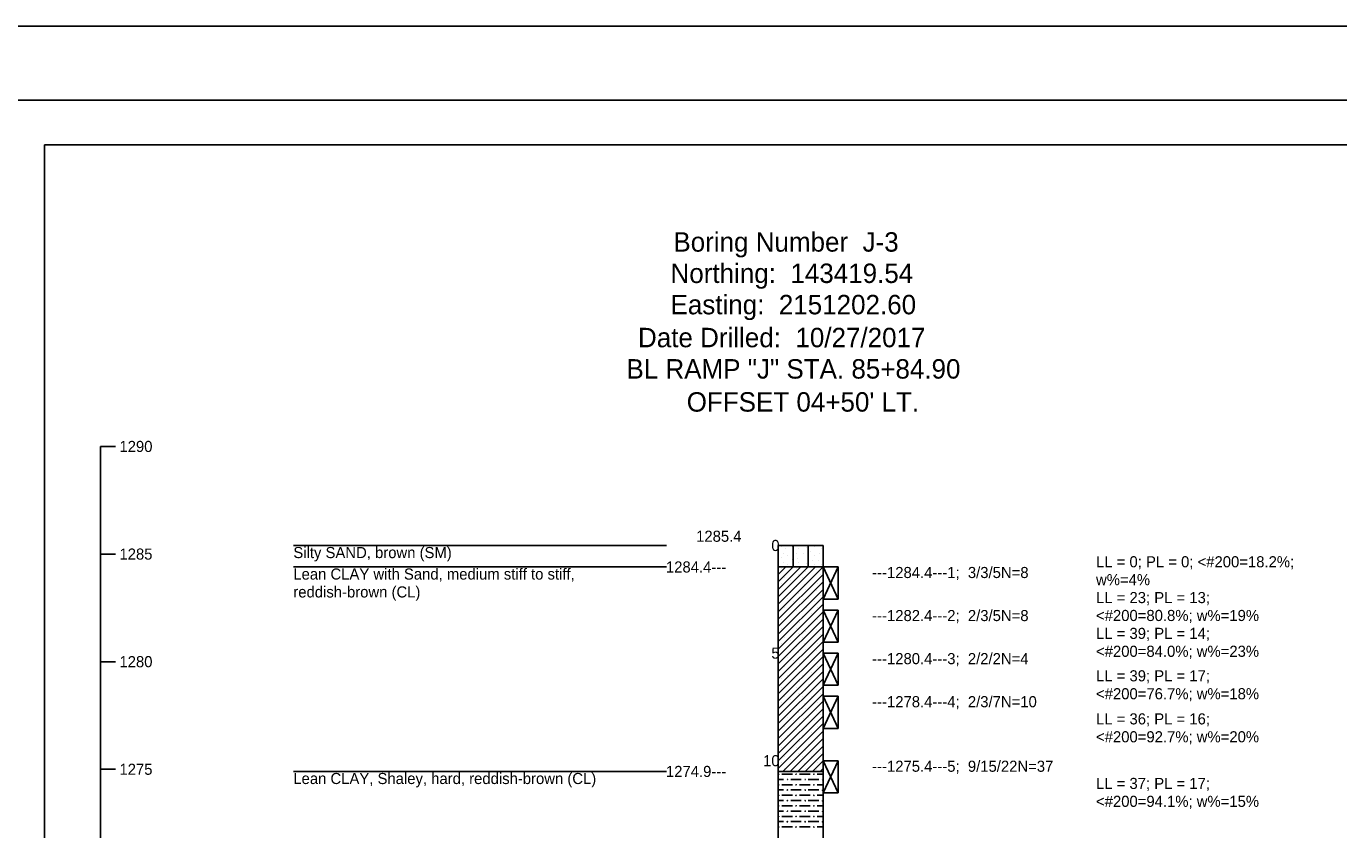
# Model space of a CAD drawing. Extents: x 2150148.6 to 2150220.1, y 143803.7 to 143875.1.
# Drawn here: x 2150167.96 to 2150182.61, y 143824.71 to 143833.69 of the extents above; entities that cross this region are included whole.
import ezdxf

# ---------------------------------------------------------------- set-up
doc = ezdxf.new("R2010")
doc.units = 0
for name, color, linetype in [('Default', 7, 'Continuous'), ('SHT_Plot_Shape_Full', 7, 'Continuous'), ('SHT_Plot_Shape_Half', 7, 'Continuous'), ('SHT_Sheet_Border', 7, 'Continuous')]:
    doc.layers.add(name, color=color, linetype=linetype)

# ---------------------------------------------------------------- blocks, each defined once
blk = doc.blocks.new('POINT_DISPLAY')
at = {"layer": 'Default'}
blk.add_line((0, 0), (0, 0), dxfattribs=at)

msp = doc.modelspace()

# ---------------------------------------------------------------- linework, layer by layer
at = {"layer": 'Default'}
msp.add_line((2150168.788, 143815.773), (2150168.788, 143828.994), dxfattribs=at)
for points in [[(2150168.788, 143828.994), (2150168.955, 143828.994)], [(2150170.94, 143827.888), (2150175.106, 143827.888)], [(2150176.356, 143827.888), (2150176.356, 143815.869)], [(2150176.356, 143827.888), (2150176.856, 143827.888)], [(2150176.523, 143827.648), (2150176.523, 143827.888)], [(2150176.69, 143827.648), (2150176.69, 143827.888)], [(2150176.856, 143827.888), (2150176.856, 143815.869)], [(2150168.788, 143827.792), (2150168.955, 143827.792)], [(2150170.94, 143827.648), (2150175.106, 143827.648)], [(2150176.356, 143827.648), (2150176.856, 143827.648)], [(2150176.356, 143827.564), (2150176.44, 143827.648)], [(2150176.356, 143827.481), (2150176.523, 143827.648)], [(2150176.356, 143827.398), (2150176.606, 143827.648)], [(2150176.356, 143827.314), (2150176.69, 143827.648)], [(2150176.356, 143827.231), (2150176.773, 143827.648)], [(2150176.356, 143827.148), (2150176.856, 143827.648)], [(2150176.356, 143827.064), (2150176.856, 143827.564)], [(2150176.856, 143827.648), (2150177.023, 143827.287)], [(2150176.856, 143827.287), (2150177.023, 143827.648)], [(2150176.856, 143827.648), (2150177.023, 143827.648)], [(2150177.023, 143827.287), (2150177.023, 143827.648)], [(2150176.356, 143826.981), (2150176.856, 143827.481)], [(2150176.356, 143826.898), (2150176.856, 143827.398)], [(2150176.356, 143826.814), (2150176.856, 143827.314)], [(2150176.356, 143826.731), (2150176.856, 143827.231)], [(2150176.856, 143827.287), (2150177.023, 143827.287)], [(2150176.356, 143826.648), (2150176.856, 143827.148)], [(2150176.856, 143827.167), (2150177.023, 143826.806)], [(2150176.856, 143826.806), (2150177.023, 143827.167)], [(2150176.856, 143827.167), (2150177.023, 143827.167)], [(2150177.023, 143826.806), (2150177.023, 143827.167)], [(2150176.356, 143826.564), (2150176.856, 143827.064)], [(2150176.356, 143826.481), (2150176.856, 143826.981)], [(2150176.356, 143826.398), (2150176.856, 143826.898)], [(2150176.356, 143826.314), (2150176.856, 143826.814)], [(2150176.856, 143826.806), (2150177.023, 143826.806)], [(2150176.356, 143826.231), (2150176.856, 143826.731)], [(2150176.356, 143826.148), (2150176.856, 143826.648)], [(2150176.856, 143826.686), (2150177.023, 143826.326)], [(2150176.856, 143826.326), (2150177.023, 143826.686)], [(2150176.856, 143826.686), (2150177.023, 143826.686)], [(2150177.023, 143826.326), (2150177.023, 143826.686)], [(2150168.788, 143826.59), (2150168.955, 143826.59)], [(2150176.356, 143826.064), (2150176.856, 143826.564)], [(2150176.356, 143825.981), (2150176.856, 143826.481)], [(2150176.356, 143825.898), (2150176.856, 143826.398)], [(2150176.356, 143825.814), (2150176.856, 143826.314)], [(2150176.356, 143825.731), (2150176.856, 143826.231)], [(2150176.856, 143826.326), (2150177.023, 143826.326)], [(2150176.856, 143826.205), (2150177.023, 143825.845)], [(2150176.856, 143825.845), (2150177.023, 143826.205)], [(2150176.856, 143826.205), (2150177.023, 143826.205)], [(2150177.023, 143825.845), (2150177.023, 143826.205)], [(2150176.356, 143825.648), (2150176.856, 143826.148)], [(2150176.356, 143825.564), (2150176.856, 143826.064)], [(2150176.356, 143825.481), (2150176.856, 143825.981)], [(2150176.356, 143825.398), (2150176.856, 143825.898)], [(2150176.406, 143825.364), (2150176.856, 143825.814)], [(2150176.856, 143825.845), (2150177.023, 143825.845)], [(2150176.489, 143825.364), (2150176.856, 143825.731)], [(2150176.573, 143825.364), (2150176.856, 143825.648)], [(2150176.656, 143825.364), (2150176.856, 143825.564)], [(2150176.739, 143825.364), (2150176.856, 143825.481)], [(2150176.856, 143825.484), (2150177.023, 143825.124)], [(2150176.856, 143825.124), (2150177.023, 143825.484)], [(2150176.856, 143825.484), (2150177.023, 143825.484)], [(2150177.023, 143825.124), (2150177.023, 143825.484)], [(2150168.788, 143825.388), (2150168.955, 143825.388)], [(2150170.94, 143825.364), (2150175.106, 143825.364)], [(2150176.356, 143825.364), (2150176.856, 143825.364)], [(2150176.356, 143825.335), (2150176.36, 143825.335), (2150176.36, 143825.331), (2150176.356, 143825.335)], [(2150176.396, 143825.335), (2150176.514, 143825.335)], [(2150176.553, 143825.335), (2150176.557, 143825.335), (2150176.553, 143825.331), (2150176.553, 143825.335)], [(2150176.593, 143825.335), (2150176.711, 143825.335)], [(2150176.75, 143825.335), (2150176.754, 143825.335), (2150176.754, 143825.331), (2150176.75, 143825.335)], [(2150176.789, 143825.335), (2150176.856, 143825.335)], [(2150176.823, 143825.364), (2150176.856, 143825.398)], [(2150176.356, 143825.275), (2150176.415, 143825.275)], [(2150176.356, 143825.216), (2150176.36, 143825.216), (2150176.36, 143825.212), (2150176.356, 143825.216)], [(2150176.396, 143825.216), (2150176.514, 143825.216)], [(2150176.455, 143825.275), (2150176.459, 143825.275), (2150176.455, 143825.272), (2150176.455, 143825.275)], [(2150176.494, 143825.275), (2150176.612, 143825.275)], [(2150176.553, 143825.216), (2150176.557, 143825.216), (2150176.553, 143825.212), (2150176.553, 143825.216)], [(2150176.593, 143825.216), (2150176.711, 143825.216)], [(2150176.652, 143825.275), (2150176.656, 143825.275), (2150176.656, 143825.272), (2150176.652, 143825.275)], [(2150176.691, 143825.275), (2150176.75, 143825.275)], [(2150176.75, 143825.275), (2150176.809, 143825.275)], [(2150176.75, 143825.216), (2150176.754, 143825.216), (2150176.754, 143825.212), (2150176.75, 143825.216)], [(2150176.789, 143825.216), (2150176.856, 143825.216)], [(2150176.848, 143825.275), (2150176.852, 143825.275), (2150176.848, 143825.272), (2150176.848, 143825.275)], [(2150176.356, 143825.157), (2150176.415, 143825.157)], [(2150176.356, 143825.098), (2150176.36, 143825.098), (2150176.36, 143825.094), (2150176.356, 143825.098)], [(2150176.356, 143825.039), (2150176.415, 143825.039)], [(2150176.396, 143825.098), (2150176.514, 143825.098)], [(2150176.455, 143825.157), (2150176.459, 143825.157), (2150176.455, 143825.153), (2150176.455, 143825.157)], [(2150176.455, 143825.039), (2150176.459, 143825.039), (2150176.455, 143825.035), (2150176.455, 143825.039)], [(2150176.494, 143825.157), (2150176.612, 143825.157)], [(2150176.494, 143825.039), (2150176.612, 143825.039)], [(2150176.553, 143825.098), (2150176.557, 143825.098), (2150176.553, 143825.094), (2150176.553, 143825.098)], [(2150176.593, 143825.098), (2150176.711, 143825.098)], [(2150176.652, 143825.157), (2150176.656, 143825.157), (2150176.656, 143825.153), (2150176.652, 143825.157)], [(2150176.652, 143825.039), (2150176.656, 143825.039), (2150176.656, 143825.035), (2150176.652, 143825.039)], [(2150176.691, 143825.157), (2150176.75, 143825.157)], [(2150176.691, 143825.039), (2150176.75, 143825.039)], [(2150176.75, 143825.157), (2150176.809, 143825.157)], [(2150176.75, 143825.098), (2150176.754, 143825.098), (2150176.754, 143825.094), (2150176.75, 143825.098)], [(2150176.75, 143825.039), (2150176.809, 143825.039)], [(2150176.789, 143825.098), (2150176.856, 143825.098)], [(2150176.848, 143825.157), (2150176.852, 143825.157), (2150176.848, 143825.153), (2150176.848, 143825.157)], [(2150176.848, 143825.039), (2150176.852, 143825.039), (2150176.848, 143825.035), (2150176.848, 143825.039)], [(2150176.856, 143825.124), (2150177.023, 143825.124)], [(2150176.356, 143824.98), (2150176.36, 143824.98), (2150176.36, 143824.976), (2150176.356, 143824.98)], [(2150176.356, 143824.921), (2150176.415, 143824.921)], [(2150176.396, 143824.98), (2150176.514, 143824.98)], [(2150176.455, 143824.921), (2150176.459, 143824.921), (2150176.455, 143824.917), (2150176.455, 143824.921)], [(2150176.494, 143824.921), (2150176.612, 143824.921)], [(2150176.553, 143824.98), (2150176.557, 143824.98), (2150176.553, 143824.976), (2150176.553, 143824.98)], [(2150176.593, 143824.98), (2150176.711, 143824.98)], [(2150176.652, 143824.921), (2150176.656, 143824.921), (2150176.656, 143824.917), (2150176.652, 143824.921)], [(2150176.691, 143824.921), (2150176.75, 143824.921)], [(2150176.75, 143824.98), (2150176.754, 143824.98), (2150176.754, 143824.976), (2150176.75, 143824.98)], [(2150176.75, 143824.921), (2150176.809, 143824.921)], [(2150176.789, 143824.98), (2150176.856, 143824.98)], [(2150176.848, 143824.921), (2150176.852, 143824.921), (2150176.848, 143824.917), (2150176.848, 143824.921)], [(2150176.356, 143824.862), (2150176.36, 143824.862), (2150176.36, 143824.858), (2150176.356, 143824.862)], [(2150176.356, 143824.803), (2150176.415, 143824.803)], [(2150176.356, 143824.744), (2150176.36, 143824.744), (2150176.36, 143824.74), (2150176.356, 143824.744)], [(2150176.396, 143824.862), (2150176.514, 143824.862)], [(2150176.396, 143824.744), (2150176.514, 143824.744)], [(2150176.455, 143824.803), (2150176.459, 143824.803), (2150176.455, 143824.799), (2150176.455, 143824.803)], [(2150176.494, 143824.803), (2150176.612, 143824.803)], [(2150176.553, 143824.862), (2150176.557, 143824.862), (2150176.553, 143824.858), (2150176.553, 143824.862)], [(2150176.553, 143824.744), (2150176.557, 143824.744), (2150176.553, 143824.74), (2150176.553, 143824.744)], [(2150176.593, 143824.862), (2150176.711, 143824.862)], [(2150176.593, 143824.744), (2150176.711, 143824.744)], [(2150176.652, 143824.803), (2150176.656, 143824.803), (2150176.656, 143824.799), (2150176.652, 143824.803)], [(2150176.691, 143824.803), (2150176.75, 143824.803)], [(2150176.75, 143824.862), (2150176.754, 143824.862), (2150176.754, 143824.858), (2150176.75, 143824.862)], [(2150176.75, 143824.803), (2150176.809, 143824.803)], [(2150176.75, 143824.744), (2150176.754, 143824.744), (2150176.754, 143824.74), (2150176.75, 143824.744)], [(2150176.789, 143824.862), (2150176.856, 143824.862)], [(2150176.789, 143824.744), (2150176.856, 143824.744)], [(2150176.848, 143824.803), (2150176.852, 143824.803), (2150176.848, 143824.799), (2150176.848, 143824.803)]]:
    msp.add_lwpolyline(points, dxfattribs=at)
at = {"layer": 'SHT_Plot_Shape_Full'}
msp.add_lwpolyline([(2150164.575, 143833.688), (2150200.575, 143833.688), (2150200.575, 143809.688), (2150164.575, 143809.688)], close=True, dxfattribs=at)
at = {"layer": 'SHT_Plot_Shape_Half'}
msp.add_lwpolyline([(2150166.212, 143832.863), (2150200.212, 143832.863), (2150200.212, 143810.863), (2150166.212, 143810.863)], close=True, dxfattribs=at)
at = {"layer": 'SHT_Sheet_Border'}
msp.add_lwpolyline([(2150199.662, 143811.363), (2150168.162, 143811.363), (2150168.162, 143832.363), (2150199.662, 143832.363)], close=True, dxfattribs=at)

# ---------------------------------------------------------------- block references
at = {"layer": 'Default', "xscale": 0.39369999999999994, "yscale": 0.3936999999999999}
for p in [(2150176.361, 143827.826), (2150176.386, 143827.876), (2150176.436, 143827.851), (2150176.511, 143827.876), (2150176.528, 143827.828), (2150176.586, 143827.851), (2150176.675, 143827.863), (2150176.711, 143827.826), (2150176.761, 143827.876), (2150176.836, 143827.851), (2150176.386, 143827.751), (2150176.411, 143827.801), (2150176.411, 143827.701), (2150176.461, 143827.776), (2150176.461, 143827.676), (2150176.511, 143827.726), (2150176.525, 143827.668), (2150176.561, 143827.801), (2150176.573, 143827.744), (2150176.586, 143827.701), (2150176.636, 143827.801), (2150176.674, 143827.687), (2150176.686, 143827.751), (2150176.742, 143827.722), (2150176.761, 143827.776), (2150176.761, 143827.676), (2150176.803, 143827.719), (2150176.811, 143827.801), (2150176.836, 143827.676), (2150176.852, 143827.726), (2150176.361, 143827.651), (2150176.362, 143827.564), (2150176.396, 143827.631), (2150176.429, 143827.531), (2150176.462, 143827.598), (2150176.562, 143827.631), (2150176.585, 143827.567), (2150176.629, 143827.531), (2150176.662, 143827.598), (2150176.711, 143827.651), (2150176.729, 143827.531), (2150176.782, 143827.614), (2150176.829, 143827.564), (2150176.396, 143827.464), (2150176.429, 143827.398), (2150176.496, 143827.498), (2150176.562, 143827.431), (2150176.646, 143827.455), (2150176.662, 143827.398), (2150176.78, 143827.38), (2150176.796, 143827.464), (2150176.362, 143827.331), (2150176.462, 143827.298), (2150176.496, 143827.364), (2150176.529, 143827.264), (2150176.581, 143827.354), (2150176.596, 143827.231), (2150176.632, 143827.284), (2150176.696, 143827.298), (2150176.762, 143827.264), (2150176.829, 143827.331), (2150176.362, 143827.131), (2150176.429, 143827.198), (2150176.462, 143827.098), (2150176.562, 143827.164), (2150176.629, 143827.098), (2150176.674, 143827.198), (2150176.729, 143827.131), (2150176.796, 143827.198), (2150176.396, 143827.064), (2150176.396, 143826.964), (2150176.562, 143826.964), (2150176.596, 143827.031), (2150176.696, 143826.998), (2150176.782, 143826.948), (2150176.796, 143827.064), (2150176.362, 143826.898), (2150176.396, 143826.798), (2150176.429, 143826.864), (2150176.462, 143826.931), (2150176.496, 143826.831), (2150176.585, 143826.901), (2150176.629, 143826.864), (2150176.646, 143826.789), (2150176.662, 143826.931), (2150176.729, 143826.864), (2150176.796, 143826.798), (2150176.829, 143826.898), (2150176.362, 143826.664), (2150176.429, 143826.731), (2150176.496, 143826.698), (2150176.562, 143826.764), (2150176.581, 143826.687), (2150176.662, 143826.731), (2150176.78, 143826.713), (2150176.829, 143826.664), (2150176.429, 143826.531), (2150176.462, 143826.631), (2150176.529, 143826.598), (2150176.562, 143826.498), (2150176.596, 143826.564), (2150176.632, 143826.617), (2150176.674, 143826.531), (2150176.696, 143826.631), (2150176.762, 143826.598), (2150176.796, 143826.531), (2150176.362, 143826.464), (2150176.396, 143826.398), (2150176.462, 143826.431), (2150176.596, 143826.364), (2150176.629, 143826.431), (2150176.729, 143826.464), (2150176.796, 143826.398), (2150176.362, 143826.231), (2150176.396, 143826.298), (2150176.462, 143826.264), (2150176.562, 143826.298), (2150176.585, 143826.234), (2150176.662, 143826.264), (2150176.696, 143826.331), (2150176.782, 143826.281), (2150176.829, 143826.231), (2150176.396, 143826.131), (2150176.429, 143826.198), (2150176.429, 143826.064), (2150176.496, 143826.164), (2150176.562, 143826.098), (2150176.629, 143826.198), (2150176.646, 143826.122), (2150176.662, 143826.064), (2150176.729, 143826.198), (2150176.796, 143826.131), (2150176.362, 143825.998), (2150176.462, 143825.964), (2150176.496, 143826.031), (2150176.529, 143825.931), (2150176.581, 143826.02), (2150176.632, 143825.951), (2150176.696, 143825.964), (2150176.762, 143825.931), (2150176.78, 143826.046), (2150176.829, 143825.998), (2150176.362, 143825.798), (2150176.429, 143825.864), (2150176.462, 143825.764), (2150176.562, 143825.831), (2150176.596, 143825.898), (2150176.629, 143825.764), (2150176.674, 143825.864), (2150176.729, 143825.798), (2150176.796, 143825.864), (2150176.396, 143825.731), (2150176.396, 143825.631), (2150176.562, 143825.631), (2150176.596, 143825.698), (2150176.696, 143825.664), (2150176.796, 143825.731), (2150176.362, 143825.564), (2150176.429, 143825.531), (2150176.462, 143825.598), (2150176.496, 143825.498), (2150176.585, 143825.567), (2150176.629, 143825.531), (2150176.662, 143825.598), (2150176.729, 143825.531), (2150176.782, 143825.614), (2150176.829, 143825.564), (2150176.396, 143825.464), (2150176.429, 143825.398), (2150176.496, 143825.364), (2150176.562, 143825.431), (2150176.646, 143825.455), (2150176.662, 143825.398), (2150176.78, 143825.38), (2150176.796, 143825.464)]:
    msp.add_blockref('POINT_DISPLAY', p, dxfattribs=at)

# ---------------------------------------------------------------- texts
at = {"layer": 'Default'}
for s, height, p in [('Boring Number  J-3', 0.217, (2150175.184, 143831.17)), ('Northing:  143419.54', 0.217, (2150175.152, 143830.82)), ('Easting:  2151202.60', 0.217, (2150175.152, 143830.47)), ('Date Drilled:  10/27/2017', 0.217, (2150174.789, 143830.102)), ('BL RAMP "J" STA. 85+84.90', 0.217, (2150174.66, 143829.752)), ("OFFSET 04+50' LT.", 0.217, (2150175.333, 143829.383)), ('1290', 0.124, (2150168.998, 143828.932)), ('1285.4', 0.124, (2150175.438, 143827.929)), ('1285', 0.124, (2150168.998, 143827.73)), ('Silty SAND, brown (SM)', 0.124, (2150170.94, 143827.747)), ('0', 0.124, (2150176.278, 143827.826)), ('1284.4---', 0.124, (2150175.101, 143827.586)), ('LL = 0; PL = 0; <#200=18.2%;', 0.124, (2150179.904, 143827.644)), ('Lean CLAY with Sand, medium stiff to stiff,', 0.124, (2150170.94, 143827.507)), ('---1284.4---1;  3/3/5N=8', 0.124, (2150177.404, 143827.524)), ('w%=4%', 0.124, (2150179.904, 143827.444)), ('reddish-brown (CL)', 0.124, (2150170.94, 143827.307)), ('LL = 23; PL = 13;', 0.124, (2150179.904, 143827.244)), ('---1282.4---2;  2/3/5N=8', 0.124, (2150177.404, 143827.043)), ('<#200=80.8%; w%=19%', 0.124, (2150179.904, 143827.044)), ('LL = 39; PL = 14;', 0.124, (2150179.904, 143826.844)), ('1280', 0.124, (2150168.998, 143826.528)), ('5', 0.124, (2150176.278, 143826.624)), ('---1280.4---3;  2/2/2N=4', 0.124, (2150177.404, 143826.562)), ('<#200=84.0%; w%=23%', 0.124, (2150179.904, 143826.644)), ('LL = 39; PL = 17;', 0.124, (2150179.904, 143826.37)), ('---1278.4---4;  2/3/7N=10', 0.124, (2150177.404, 143826.081)), ('<#200=76.7%; w%=18%', 0.124, (2150179.904, 143826.17)), ('LL = 36; PL = 16;', 0.124, (2150179.904, 143825.889)), ('<#200=92.7%; w%=20%', 0.124, (2150179.904, 143825.689)), ('10', 0.124, (2150176.186, 143825.422)), ('---1275.4---5;  9/15/22N=37', 0.124, (2150177.404, 143825.36)), ('1275', 0.124, (2150168.998, 143825.326)), ('Lean CLAY, Shaley, hard, reddish-brown (CL)', 0.124, (2150170.94, 143825.223)), ('1274.9---', 0.124, (2150175.101, 143825.302)), ('LL = 37; PL = 17;', 0.124, (2150179.904, 143825.168)), ('<#200=94.1%; w%=15%', 0.124, (2150179.904, 143824.968))]:
    msp.add_text(s, height=height, dxfattribs=at).set_placement(p)

doc.saveas('drawing.dxf')
